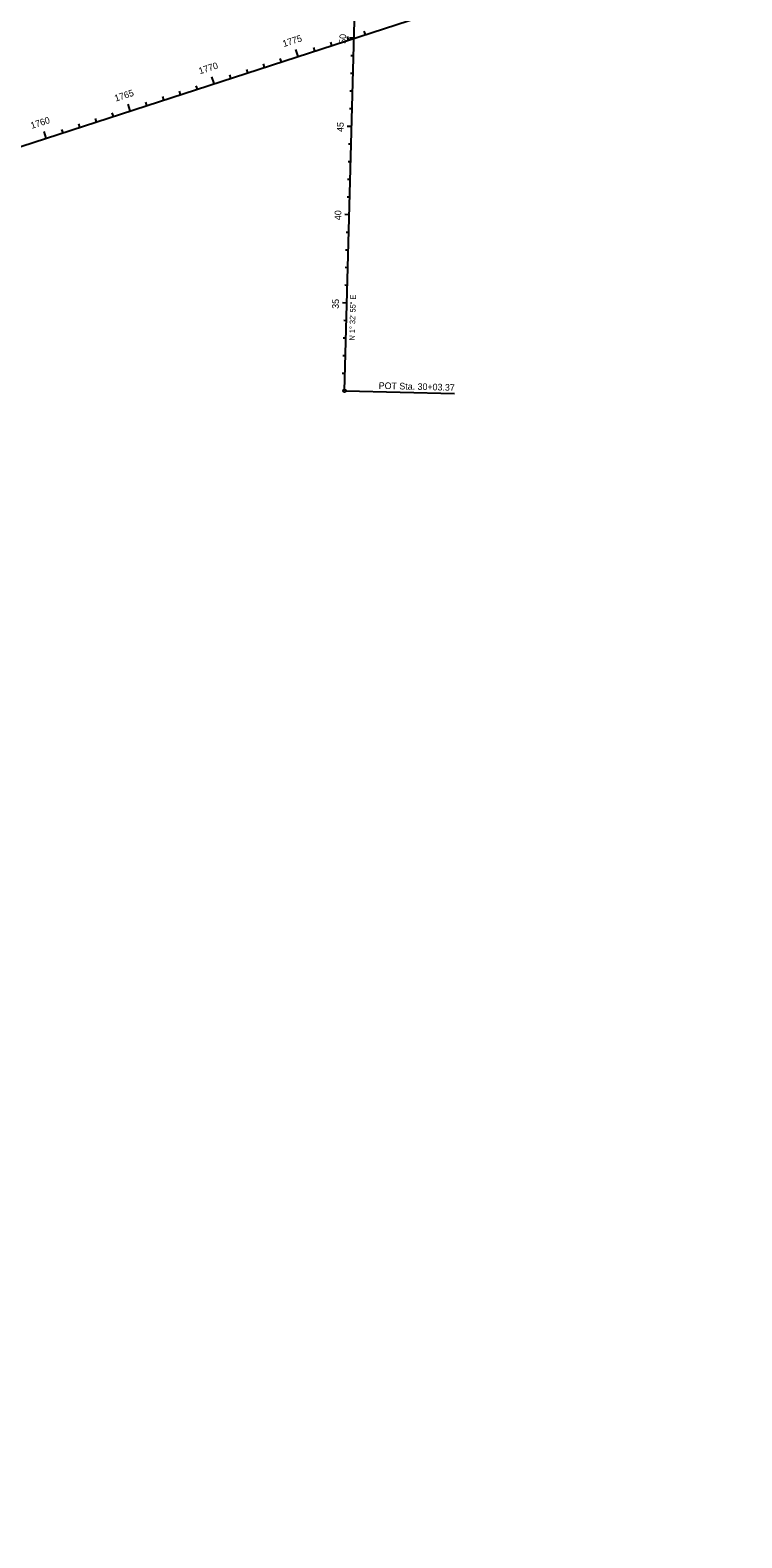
# Model space of a CAD drawing. Extents: x 1280727 to 1452510, y 526233 to 601451.
# Drawn here: x 1431319 to 1435349, y 577660 to 586198 of the extents above; entities that cross this region are included whole.
import ezdxf

# ---------------------------------------------------------------- set-up
doc = ezdxf.new("R2010")
doc.units = 0
for name, color, linetype in [('RW_X_CL', 7, 'Continuous'), ('RW_X_CL_500_Stations', 7, 'Continuous'), ('SH_Text', 7, 'Continuous')]:
    doc.layers.add(name, color=color, linetype=linetype)

msp = doc.modelspace()

# ---------------------------------------------------------------- linework, layer by layer
at = {"layer": 'RW_X_CL'}
for p, q in [((1433098.9, 584156.4), (1433242.7, 589473.8)), ((1406994.9, 577659.9), (1435349.1, 586865.3))]:
    msp.add_line(p, q, dxfattribs=at)
at = {"layer": 'RW_X_CL_500_Stations'}
for p, q in [((1433122, 586142.3), (1433115.9, 586161.3)), ((1433152.9, 586152.3), (1433127.9, 586153)), ((1433217.2, 586173.2), (1433211, 586192.2)), ((1432836.7, 586049.7), (1432824.4, 586087.7)), ((1432931.8, 586080.5), (1432925.6, 586099.6)), ((1433026.9, 586111.4), (1433020.8, 586130.4)), ((1432551.4, 585957), (1432545.2, 585976)), ((1432646.5, 585987.9), (1432640.3, 586006.9)), ((1432741.6, 586018.8), (1432735.4, 586037.8)), ((1433150.2, 586052.3), (1433135.2, 586052.7)), ((1432361.1, 585895.3), (1432348.8, 585933.3)), ((1432456.3, 585926.1), (1432450.1, 585945.2)), ((1433147.5, 585952.4), (1433132.5, 585952.8)), ((1432075.8, 585802.6), (1432069.6, 585821.6)), ((1432170.9, 585833.5), (1432164.7, 585852.5)), ((1432266, 585864.4), (1432259.9, 585883.4)), ((1433144.8, 585852.4), (1433129.8, 585852.8)), ((1431790.5, 585710), (1431784.3, 585729)), ((1431885.6, 585740.9), (1431873.2, 585778.9)), ((1431980.7, 585771.7), (1431974.5, 585790.8)), ((1433142.1, 585752.5), (1433127.1, 585752.9)), ((1431505.1, 585617.3), (1431499, 585636.4)), ((1431600.2, 585648.2), (1431594.1, 585667.2)), ((1431695.4, 585679.1), (1431689.2, 585698.1)), ((1433139.4, 585652.5), (1433114.4, 585653.2)), ((1431410, 585586.5), (1431397.7, 585624.5)), ((1433136.7, 585552.5), (1433121.7, 585552.9)), ((1433134, 585452.6), (1433119, 585453)), ((1433131.3, 585352.6), (1433116.3, 585353)), ((1433128.6, 585252.6), (1433113.6, 585253)), ((1433125.9, 585152.7), (1433100.9, 585153.3)), ((1433123.2, 585052.7), (1433108.2, 585053.1)), ((1433120.5, 584952.7), (1433105.5, 584953.1)), ((1433117.8, 584852.8), (1433102.8, 584853.2)), ((1433115.1, 584752.8), (1433100.1, 584753.2)), ((1433112.4, 584652.9), (1433087.4, 584653.5)), ((1433109.7, 584552.9), (1433094.7, 584553.3)), ((1433107, 584452.9), (1433092, 584453.3)), ((1433104.3, 584353), (1433089.3, 584353.4)), ((1433101.6, 584253), (1433086.6, 584253.4))]:
    msp.add_line(p, q, dxfattribs=at)
at = {"layer": 'SH_Text'}
msp.add_line((1433106.4, 584156.2), (1433722.1, 584139.6), dxfattribs=at)
msp.add_circle((1433098.9, 584156.4), 7.5, dxfattribs=at)

# ---------------------------------------------------------------- texts
at = {"layer": 'RW_X_CL_500_Stations'}
for s, rotation, p in [('1775', 17.98637, (1432755.6, 586102.2)), ('50', 88.45126, (1433107, 586120.3)), ('1770', 17.98637, (1432280.4, 585947.9)), ('1765', 17.98637, (1431803.6, 585793.1)), ('1760', 17.98637, (1431328.4, 585638.8)), ('45', 88.45126, (1433093.5, 585621.1)), ('40', 88.45126, (1433080, 585121.7)), ('35', 88.45126, (1433066.4, 584619.5))]:
    msp.add_text(s, height=37.5, rotation=rotation, dxfattribs=at).set_placement(p)
at = {"layer": 'SH_Text'}
for s, height, rotation, p in [('N 1° 32\' 55" E', 31.2, 88.45126, (1433156.9, 584439.9)), ('POT Sta. 30+03.37', 37.5, 358.45126, (1433292.4, 584167))]:
    msp.add_text(s, height=height, rotation=rotation, dxfattribs=at).set_placement(p)

doc.saveas('drawing.dxf')
